// Mitsubishi GX Works2 project: MC-56MR-6MT-F800A-FX-A例程   PLC: FX1S

PROGRAM MAIN
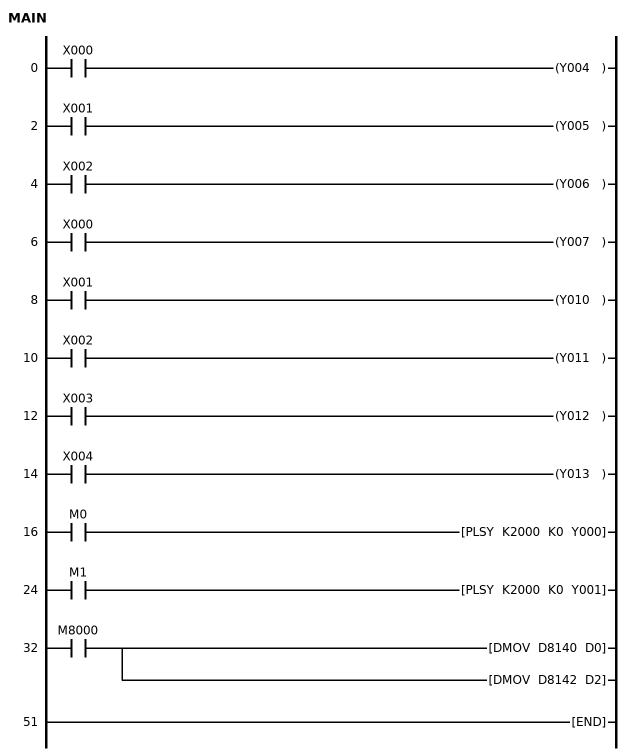
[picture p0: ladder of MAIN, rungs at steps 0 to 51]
0     LD      X000
      OUT     Y004
2     LD      X001
      OUT     Y005
4     LD      X002
      OUT     Y006
6     LD      X000
      OUT     Y007
8     LD      X001
      OUT     Y010
10    LD      X002
      OUT     Y011
12    LD      X003
      OUT     Y012
14    LD      X004
      OUT     Y013
16    LD      M0
      PLSY    K2000 K0 Y000
24    LD      M1
      PLSY    K2000 K0 Y001
32    LD      M8000
      DMOV    D8140 D0
      DMOV    D8142 D2
51    END
END_PROGRAM
